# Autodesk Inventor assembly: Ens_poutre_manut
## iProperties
Shininess: 64.0
Length Units: 11269
Angle Units: 11279
Time Units: 11290
Mass Units: 11283
Length Display Precision: 3
Angle Display Precision: 2
Compacted: True
Created: 2008-04
Part Number: Ens_poutre_manut
Document SubType Name: Assembly
Designer: Pascal
Density: 0.0
Volumn: 0.0
Area: 0.0
PropertySet Name: Model Information
Control State: 0
Master: False
Checked Out: False
Author: Pascal
